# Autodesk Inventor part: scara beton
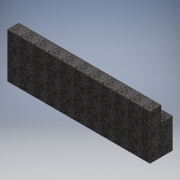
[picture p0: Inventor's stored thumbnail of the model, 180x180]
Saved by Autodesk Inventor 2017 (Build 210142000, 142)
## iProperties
Created: 2017-11
Part Number: scara beton
Material: Concrete
Document SubType Name: Modeling
Designer: iusti
Density: 2.40731 g/cm^3
Appearance: Exposed Aggregate - Coarse
Author: iusti
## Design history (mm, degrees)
sketch "Sketch1"
  geometry: L1 (0, 0)-(300, 0); L2 (300, 0)-(300, 400); L3 (300, 400)-(150, 400); L4 (150, 400)-(150, 600); L5 (150, 600)-(0, 600); L6 (0, 600)-(0, 0)
  constraints: 12 end point, 5 perpendicular, 1 horizontal
  dimensions: "d0" = 300 distance of L1.start L1.end; "d1" = 400 distance of L1.end L2.end; "d2" = 90 deg angle of L2 L1 (derived); "d3" = 150 distance of L2.end L3.end; "d4" = 200 distance of L3.end L4.end
extrude "Extrusion1" new body sketch "Sketch1" distance "d5" = 1900; taper "d6" = 0 deg
body "Solid1"
